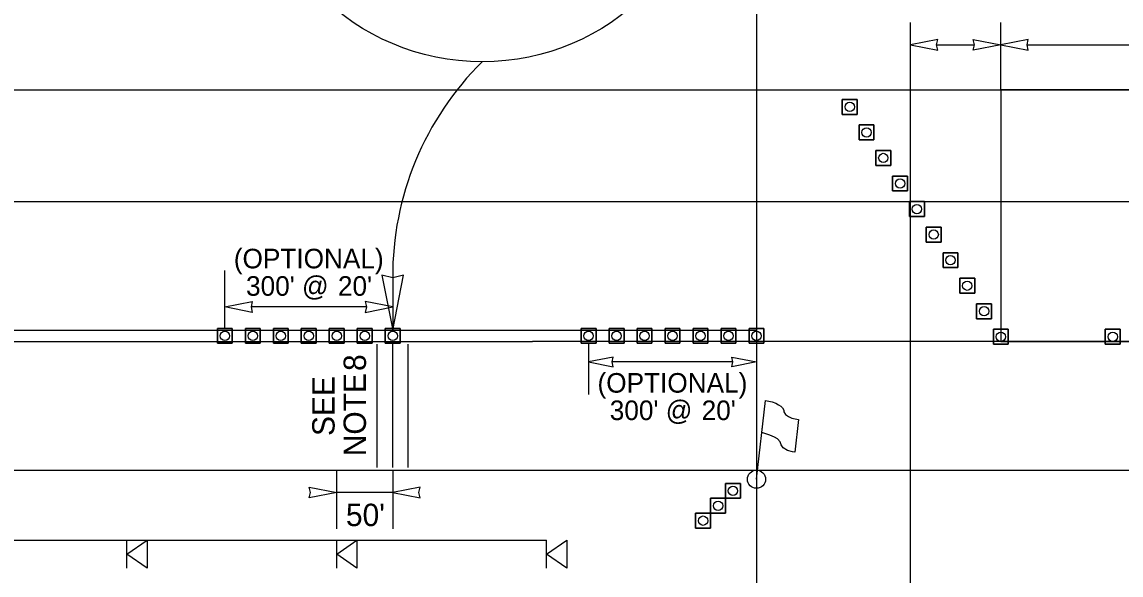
# Model space of a CAD drawing. Extents: x 99999.1 to 100095.7, y 99995 to 100010.7.
# Drawn here: x 100041.652 to 100045.58, y 100005.757 to 100007.734 of the extents above; entities that cross this region are included whole.
import ezdxf

# ---------------------------------------------------------------- set-up
doc = ezdxf.new("R2010")
doc.units = 0
for name, color, linetype in [('RD_ED_ShoulderPavedEdge', 7, 'Continuous'), ('RD_MK_LineDblYellowCenter', 7, 'Continuous'), ('RD_MK_LineEdgeWhite', 7, 'Continuous'), ('RD_MK_LineNoPass', 7, 'Continuous'), ('RD_MK_LineSkipCenter', 7, 'Continuous'), ('TR_WZ_FlaggingStation', 7, 'Continuous'), ('TR_WZ_PortableSignMountBlk-Org', 7, 'Continuous'), ('TR_WZ_TrafficCone', 7, 'Continuous'), ('TR_WZ_WorkZoneDetails', 7, 'Continuous'), ('TR_WZ_WorkZoneTextCurrent', 7, 'Continuous')]:
    doc.layers.add(name, color=color, linetype=linetype)

msp = doc.modelspace()

# ---------------------------------------------------------------- linework, layer by layer
at = {"layer": 'RD_ED_ShoulderPavedEdge'}
msp.add_line((100040.1076, 100007.4923), (100055.6424, 100007.4923), dxfattribs=at)
at = {"layer": 'RD_MK_LineDblYellowCenter'}
for p, q in [((100040.1282, 100006.6323), (100043.4767, 100006.6323)), ((100040.0869, 100006.5923), (100043.4767, 100006.5923))]:
    msp.add_line(p, q, dxfattribs=at)
at = {"layer": 'RD_MK_LineEdgeWhite'}
for p, q in [((100040.1076, 100007.0923), (100055.6424, 100007.0923)), ((100040.1076, 100006.1323), (100055.6424, 100006.1323))]:
    msp.add_line(p, q, dxfattribs=at)
at = {"layer": 'RD_MK_LineNoPass'}
msp.add_line((100043.4767, 100006.6323), (100044.2767, 100006.6323), dxfattribs=at)
at = {"layer": 'RD_MK_LineSkipCenter'}
msp.add_lwpolyline([(100051.15, 100006.5923), (100043.4767, 100006.5923)], dxfattribs=at)
at = {"layer": 'TR_WZ_FlaggingStation'}
for p, q in [((100044.2767, 100006.0998), (100044.3087, 100006.3808)), ((100044.2957, 100006.2667), (100044.3087, 100006.3811)), ((100044.4267, 100006.3133), (100044.4134, 100006.1961)), ((100044.2957, 100006.2667), (100044.2957, 100006.2667))]:
    msp.add_line(p, q, dxfattribs=at)
for points in [[(100044.3087, 100006.3811), (100044.3145, 100006.3798), (100044.3323, 100006.3764), (100044.3461, 100006.3722), (100044.3558, 100006.3661), (100044.3643, 100006.3614), (100044.37, 100006.3546), (100044.3743, 100006.3467), (100044.3748, 100006.3405), (100044.3802, 100006.3313), (100044.391, 100006.3239), (100044.4034, 100006.3187), (100044.4267, 100006.3133)], [(100044.4134, 100006.1961), (100044.4052, 100006.1975), (100044.3876, 100006.2021), (100044.3719, 100006.2126), (100044.3654, 100006.2232), (100044.3615, 100006.2335), (100044.3524, 100006.2444), (100044.3414, 100006.2506), (100044.3241, 100006.2577), (100044.2957, 100006.2667)]]:
    msp.add_lwpolyline(points, dxfattribs=at)
msp.add_circle((100044.2767, 100006.0998), 0.0325, dxfattribs=at)
at = {"layer": 'TR_WZ_PortableSignMountBlk-Org'}
for p, q in [((100042.0267, 100005.7824), (100042.0267, 100005.8824)), ((100042.7767, 100005.7824), (100042.7767, 100005.8824)), ((100043.5267, 100005.7824), (100043.5267, 100005.8824))]:
    msp.add_line(p, q, dxfattribs=at)
for points in [[(100042.0267, 100005.8323), (100042.0985, 100005.8824), (100042.0985, 100005.7824)], [(100042.7767, 100005.8323), (100042.8485, 100005.8824), (100042.8485, 100005.7824)], [(100043.5267, 100005.8323), (100043.5985, 100005.8824), (100043.5985, 100005.7824)]]:
    msp.add_lwpolyline(points, close=True, dxfattribs=at)
at = {"layer": 'TR_WZ_TrafficCone'}
for points in [[(100044.6367, 100007.4577), (100044.5834, 100007.4577), (100044.5834, 100007.4043), (100044.6367, 100007.4043), (100044.6367, 100007.4577)], [(100044.6367, 100007.4043), (100044.5834, 100007.4043), (100044.5834, 100007.4577), (100044.6367, 100007.4577), (100044.6367, 100007.4043)], [(100044.6967, 100007.3663), (100044.6434, 100007.3663), (100044.6434, 100007.313), (100044.6967, 100007.313), (100044.6967, 100007.3663)], [(100044.6967, 100007.313), (100044.6434, 100007.313), (100044.6434, 100007.3663), (100044.6967, 100007.3663), (100044.6967, 100007.313)], [(100044.7567, 100007.275), (100044.7034, 100007.275), (100044.7034, 100007.2217), (100044.7567, 100007.2217), (100044.7567, 100007.275)], [(100044.7567, 100007.2217), (100044.7034, 100007.2217), (100044.7034, 100007.275), (100044.7567, 100007.275), (100044.7567, 100007.2217)], [(100044.8167, 100007.1837), (100044.7634, 100007.1837), (100044.7634, 100007.1303), (100044.8167, 100007.1303), (100044.8167, 100007.1837)], [(100044.8167, 100007.1303), (100044.7634, 100007.1303), (100044.7634, 100007.1837), (100044.8167, 100007.1837), (100044.8167, 100007.1303)], [(100044.8234, 100007.0923), (100044.8767, 100007.0923), (100044.8767, 100007.039), (100044.8234, 100007.039), (100044.8234, 100007.0923)], [(100044.8234, 100007.039), (100044.8767, 100007.039), (100044.8767, 100007.0923), (100044.8234, 100007.0923), (100044.8234, 100007.039)], [(100044.8834, 100007.001), (100044.9367, 100007.001), (100044.9367, 100006.9477), (100044.8834, 100006.9477), (100044.8834, 100007.001)], [(100044.8834, 100006.9477), (100044.9367, 100006.9477), (100044.9367, 100007.001), (100044.8834, 100007.001), (100044.8834, 100006.9477)], [(100044.9434, 100006.9097), (100044.9967, 100006.9097), (100044.9967, 100006.8563), (100044.9434, 100006.8563), (100044.9434, 100006.9097)], [(100044.9434, 100006.8563), (100044.9967, 100006.8563), (100044.9967, 100006.9097), (100044.9434, 100006.9097), (100044.9434, 100006.8563)], [(100045.0034, 100006.8183), (100045.0567, 100006.8183), (100045.0567, 100006.765), (100045.0034, 100006.765), (100045.0034, 100006.8183)], [(100045.0034, 100006.765), (100045.0567, 100006.765), (100045.0567, 100006.8183), (100045.0034, 100006.8183), (100045.0034, 100006.765)], [(100045.0634, 100006.727), (100045.1167, 100006.727), (100045.1167, 100006.6737), (100045.0634, 100006.6737), (100045.0634, 100006.727)], [(100045.0634, 100006.6737), (100045.1167, 100006.6737), (100045.1167, 100006.727), (100045.0634, 100006.727), (100045.0634, 100006.6737)], [(100042.4033, 100006.639), (100042.35, 100006.639), (100042.35, 100006.5857), (100042.4033, 100006.5857), (100042.4033, 100006.639)], [(100042.4033, 100006.5857), (100042.35, 100006.5857), (100042.35, 100006.639), (100042.4033, 100006.639), (100042.4033, 100006.5857)], [(100042.5033, 100006.639), (100042.45, 100006.639), (100042.45, 100006.5857), (100042.5033, 100006.5857), (100042.5033, 100006.639)], [(100042.5033, 100006.5857), (100042.45, 100006.5857), (100042.45, 100006.639), (100042.5033, 100006.639), (100042.5033, 100006.5857)], [(100042.6033, 100006.639), (100042.55, 100006.639), (100042.55, 100006.5857), (100042.6033, 100006.5857), (100042.6033, 100006.639)], [(100042.6033, 100006.5857), (100042.55, 100006.5857), (100042.55, 100006.639), (100042.6033, 100006.639), (100042.6033, 100006.5857)], [(100042.7033, 100006.639), (100042.65, 100006.639), (100042.65, 100006.5857), (100042.7033, 100006.5857), (100042.7033, 100006.639)], [(100042.7033, 100006.5857), (100042.65, 100006.5857), (100042.65, 100006.639), (100042.7033, 100006.639), (100042.7033, 100006.5857)], [(100042.8033, 100006.639), (100042.75, 100006.639), (100042.75, 100006.5857), (100042.8033, 100006.5857), (100042.8033, 100006.639)], [(100042.8033, 100006.5857), (100042.75, 100006.5857), (100042.75, 100006.639), (100042.8033, 100006.639), (100042.8033, 100006.5857)], [(100042.9033, 100006.639), (100042.85, 100006.639), (100042.85, 100006.5857), (100042.9033, 100006.5857), (100042.9033, 100006.639)], [(100042.9033, 100006.5857), (100042.85, 100006.5857), (100042.85, 100006.639), (100042.9033, 100006.639), (100042.9033, 100006.5857)], [(100043.0033, 100006.639), (100042.95, 100006.639), (100042.95, 100006.5857), (100043.0033, 100006.5857), (100043.0033, 100006.639)], [(100043.0033, 100006.5857), (100042.95, 100006.5857), (100042.95, 100006.639), (100043.0033, 100006.639), (100043.0033, 100006.5857)], [(100043.7033, 100006.639), (100043.65, 100006.639), (100043.65, 100006.5857), (100043.7033, 100006.5857), (100043.7033, 100006.639)], [(100043.7033, 100006.5857), (100043.65, 100006.5857), (100043.65, 100006.639), (100043.7033, 100006.639), (100043.7033, 100006.5857)], [(100043.8033, 100006.639), (100043.75, 100006.639), (100043.75, 100006.5857), (100043.8033, 100006.5857), (100043.8033, 100006.639)], [(100043.8033, 100006.5857), (100043.75, 100006.5857), (100043.75, 100006.639), (100043.8033, 100006.639), (100043.8033, 100006.5857)], [(100043.9033, 100006.639), (100043.85, 100006.639), (100043.85, 100006.5857), (100043.9033, 100006.5857), (100043.9033, 100006.639)], [(100043.9033, 100006.5857), (100043.85, 100006.5857), (100043.85, 100006.639), (100043.9033, 100006.639), (100043.9033, 100006.5857)], [(100044.0033, 100006.639), (100043.95, 100006.639), (100043.95, 100006.5857), (100044.0033, 100006.5857), (100044.0033, 100006.639)], [(100044.0033, 100006.5857), (100043.95, 100006.5857), (100043.95, 100006.639), (100044.0033, 100006.639), (100044.0033, 100006.5857)], [(100044.1033, 100006.639), (100044.05, 100006.639), (100044.05, 100006.5857), (100044.1033, 100006.5857), (100044.1033, 100006.639)], [(100044.1033, 100006.5857), (100044.05, 100006.5857), (100044.05, 100006.639), (100044.1033, 100006.639), (100044.1033, 100006.5857)], [(100044.2033, 100006.639), (100044.15, 100006.639), (100044.15, 100006.5857), (100044.2033, 100006.5857), (100044.2033, 100006.639)], [(100044.2033, 100006.5857), (100044.15, 100006.5857), (100044.15, 100006.639), (100044.2033, 100006.639), (100044.2033, 100006.5857)], [(100044.3033, 100006.639), (100044.25, 100006.639), (100044.25, 100006.5857), (100044.3033, 100006.5857), (100044.3033, 100006.639)], [(100044.3033, 100006.5857), (100044.25, 100006.5857), (100044.25, 100006.639), (100044.3033, 100006.639), (100044.3033, 100006.5857)], [(100045.1234, 100006.6357), (100045.1767, 100006.6357), (100045.1767, 100006.5823), (100045.1234, 100006.5823), (100045.1234, 100006.6357)], [(100045.1234, 100006.5823), (100045.1767, 100006.5823), (100045.1767, 100006.6357), (100045.1234, 100006.6357), (100045.1234, 100006.5823)], [(100045.5234, 100006.6357), (100045.5767, 100006.6357), (100045.5767, 100006.5823), (100045.5234, 100006.5823), (100045.5234, 100006.6357)], [(100045.5234, 100006.5823), (100045.5767, 100006.5823), (100045.5767, 100006.6357), (100045.5234, 100006.6357), (100045.5234, 100006.5823)], [(100044.166, 100006.085), (100044.2193, 100006.085), (100044.2193, 100006.0317), (100044.166, 100006.0317), (100044.166, 100006.085)], [(100044.166, 100006.0317), (100044.2193, 100006.0317), (100044.2193, 100006.085), (100044.166, 100006.085), (100044.166, 100006.0317)], [(100044.1127, 100006.0317), (100044.166, 100006.0317), (100044.166, 100005.9783), (100044.1127, 100005.9783), (100044.1127, 100006.0317)], [(100044.1127, 100005.9783), (100044.166, 100005.9783), (100044.166, 100006.0317), (100044.1127, 100006.0317), (100044.1127, 100005.9783)], [(100044.0593, 100005.9783), (100044.1127, 100005.9783), (100044.1127, 100005.925), (100044.0593, 100005.925), (100044.0593, 100005.9783)], [(100044.0593, 100005.925), (100044.1127, 100005.925), (100044.1127, 100005.9783), (100044.0593, 100005.9783), (100044.0593, 100005.925)]]:
    msp.add_lwpolyline(points, dxfattribs=at)
for centre in [(100044.61, 100007.431), (100044.67, 100007.3397), (100044.73, 100007.2483), (100044.79, 100007.157), (100044.85, 100007.0657), (100044.91, 100006.9743), (100044.97, 100006.883), (100045.03, 100006.7917), (100045.09, 100006.7003), (100042.3767, 100006.6123), (100042.4767, 100006.6123), (100042.5767, 100006.6123), (100042.6767, 100006.6123), (100042.7767, 100006.6123), (100042.8767, 100006.6123), (100042.9767, 100006.6123), (100043.6767, 100006.6123), (100043.7767, 100006.6123), (100043.8767, 100006.6123), (100043.9767, 100006.6123), (100044.0767, 100006.6123), (100044.1767, 100006.6123), (100044.2767, 100006.6123), (100045.15, 100006.609), (100045.55, 100006.609), (100044.1927, 100006.0583), (100044.1393, 100006.005), (100044.086, 100005.9517)]:
    msp.add_circle(centre, 0.0167, dxfattribs=at)
at = {"layer": 'TR_WZ_WorkZoneDetails'}
for p, q in [((100044.2767, 100008.9491), (100044.2767, 100005.4923)), ((100044.8267, 100005.4923), (100044.8267, 100007.7323)), ((100045.15, 100007.4923), (100045.15, 100007.7323)), ((100044.9204, 100007.6523), (100045.0563, 100007.6523)), ((100045.2437, 100007.6523), (100049.84, 100007.6523)), ((100042.3767, 100006.6357), (100042.3767, 100006.8457)), ((100042.9767, 100006.8457), (100042.9767, 100006.6357)), ((100042.8829, 100006.7157), (100042.4704, 100006.7157)), ((100042.921, 100006.1423), (100042.921, 100006.5823)), ((100042.9767, 100006.1423), (100042.9767, 100006.5823)), ((100043.0315, 100006.1423), (100043.0315, 100006.5823)), ((100043.6767, 100006.5857), (100043.6767, 100006.4023)), ((100044.1923, 100006.5193), (100043.761, 100006.5193)), ((100042.7767, 100005.9223), (100042.7767, 100006.1323)), ((100042.9767, 100006.1323), (100042.9767, 100005.9223)), ((100042.9767, 100006.0523), (100042.7767, 100006.0523)), ((100040.5267, 100005.8824), (100043.5267, 100005.8824))]:
    msp.add_line(p, q, dxfattribs=at)
for points in [[(100044.8267, 100007.6523), (100044.9249, 100007.6331), (100044.9204, 100007.6523), (100044.9249, 100007.6716)], [(100045.15, 100007.6523), (100045.0517, 100007.6331), (100045.0563, 100007.6523), (100045.0517, 100007.6716)], [(100045.15, 100007.6523), (100045.2483, 100007.6331), (100045.2437, 100007.6523), (100045.2483, 100007.6716)], [(100045.15, 100007.4923), (100045.15, 100006.5923), (100049.9338, 100006.5923), (100049.9338, 100007.4923)], [(100042.9767, 100006.6323), (100043.0152, 100006.8289), (100042.9767, 100006.8198), (100042.9381, 100006.8289)], [(100042.3767, 100006.7157), (100042.4749, 100006.7349), (100042.4704, 100006.7157), (100042.4749, 100006.6964)], [(100042.9767, 100006.7157), (100042.8784, 100006.7349), (100042.8829, 100006.7157), (100042.8784, 100006.6964)], [(100043.6767, 100006.5193), (100043.7651, 100006.502), (100043.761, 100006.5193), (100043.7651, 100006.5367)], [(100044.2767, 100006.5193), (100044.1882, 100006.502), (100044.1923, 100006.5193), (100044.1882, 100006.5367)], [(100042.7767, 100006.0523), (100042.6784, 100006.0331), (100042.6829, 100006.0523), (100042.6784, 100006.0716)], [(100042.9767, 100006.0523), (100043.0749, 100006.0331), (100043.0704, 100006.0523), (100043.0749, 100006.0716)]]:
    msp.add_lwpolyline(points, close=True, dxfattribs=at)
msp.add_circle((100043.2965, 100008.4168), 0.8245, dxfattribs=at)
msp.add_arc((100044.0525, 100006.8268), 1.0759, 134.6391, 180.3733, dxfattribs=at)

# ---------------------------------------------------------------- texts
for s, p in [('8', (100042.881, 100006.4868)), ('SEE', (100042.769, 100006.2544)), ('NOTE', (100042.881, 100006.182))]:
    msp.add_text(s, height=0.08, rotation=90, dxfattribs=at).set_placement(p)
at = {"layer": 'TR_WZ_WorkZoneTextCurrent'}
for s, height, p in [('(OPTIONAL)', 0.07, (100042.4087, 100006.8537)), ("300' @", 0.07, (100042.4524, 100006.7557)), ("20'", 0.07, (100042.7808, 100006.7557)), ('(OPTIONAL)', 0.07, (100043.7085, 100006.4093)), ("300' @", 0.07, (100043.7523, 100006.3113)), ("20'", 0.07, (100044.0807, 100006.3113)), ("50'", 0.08, (100042.8094, 100005.9323))]:
    msp.add_text(s, height=height, dxfattribs=at).set_placement(p)

doc.saveas('drawing.dxf')
